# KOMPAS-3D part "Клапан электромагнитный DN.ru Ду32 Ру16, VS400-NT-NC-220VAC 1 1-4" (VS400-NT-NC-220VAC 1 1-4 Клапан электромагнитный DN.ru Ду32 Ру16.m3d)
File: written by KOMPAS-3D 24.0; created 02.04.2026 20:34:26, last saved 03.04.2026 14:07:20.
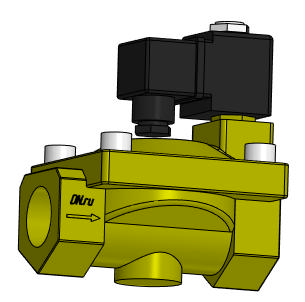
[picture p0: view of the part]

Document properties: Автор: artio; Полное имя файла: C:\Users\artio\OneDrive\Рабочий стол\Клапан электромагнитный DN.ru VS4x-xT-NC-x\VS400-NT-NC\VS400-NT-NC-220VAC 1 1-4 Клапан электромагнитный DN.ru Ду32 Ру16.m3d

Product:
- Body: Тело 1  | qty 1
    Масса: 4.144257
- Part/product: Клапан электромагнитный DN.ru Ду32 Ру16  | designation VS400-NT-NC-220VAC 1 1-4
    Масса: 2.569
    Раздел спецификации: Прочие изделия
    Примечание: D130-04664
    additional columns: ef56311e-7521-43dc-8291-0e6108b3d81d; VS400-ET-NC-220VAC 1 1-4; artio; c; Шероховатость не задана; Да

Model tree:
1. Операция без истории:1

Expressions: VS400-NT-NC-220VAC 1 1-4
